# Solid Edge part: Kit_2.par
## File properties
Sűrűség: 0,000 kg/m^3
Pontosság: 0,990
Author: ahadarics
Last saved by: psaghy
Revision: 79
Username: ahadarics
Dokumentum tartalom típus: 0
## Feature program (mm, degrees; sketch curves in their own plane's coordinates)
base feature "unnamed BaseFeature 1"
sketch for "Furat_1" plane through (0, 0, 32.5) normal (0, 0, 1) x-axis (0, -1, 0)
  hole centre (-16.25, 16.25) bore radius 2.4585
hole "Furat_1" nominal diameter 6 finite  VBottomAngle = 118 deg
sketch for "unnamed Hole 1" plane through (0, 0, 32.5) normal (0, 0, 1) x-axis (0, -1, 0)
  hole centre (-16.25, -16.25) bore radius 2.4585
hole "unnamed Hole 1" finite
sketch for "unnamed Hole 2" plane through (0, 0, 32.5) normal (0, 0, 1) x-axis (0, -1, 0)
  hole centre (16.25, -16.25) bore radius 2.4585
hole "unnamed Hole 2" finite
sketch for "unnamed Hole 3" plane through (0, 0, 32.5) normal (0, 0, 1) x-axis (0, -1, 0)
  hole centre (16.25, 16.25) bore radius 2.4585
hole "unnamed Hole 3" finite
pattern "unnamed Pattern 1" of "Furat_1", "unnamed Hole 1", "unnamed Hole 2", "unnamed Hole 3"
sketch for "Furat_5" plane through (23.5, 0.0133, 16.7488) normal (1, 0, 0) x-axis (0, 0, 1)
hole "Furat_5" diameter 9.728 finite  ThreadDepth = 9 mm
chamfer "Letörés_1" setback 0.9
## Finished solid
Body 1: solid body, 352 faces, 833 edges, 526 vertices, 4 internal voids.
  Faces by surface: cylinder 126, plane 118, cone 33, torus 33, spline 30, sphere 10, swept 2
  Edges by curve: curve on surface 298, line 276, circle 245, spline 14
Bounding box of the edges (mm; curved faces can reach further): 47.001 x 47.000 x 30.500, from (-23.5, -23.5, 6) to (23.5005, 23.5, 36.5).
Cylindrical faces by radius (mm): R0.2287 x1, R0.2297 x1, R0.2305 x1, R0.232 x1, R0.2354 x1, R0.2616 x1, R0.2684 x1, R0.2696 x1, R0.274 x1, R0.2809 x1, R0.2869 x1, R0.2897 x2, R0.2949 x1, R0.2975 x1, R0.2999 x1, R0.3047 x1, R0.3049 x1, R0.3054 x1, R0.3191 x1, R0.3251 x1, R0.3471 x1, R0.361 x1, R0.3789 x1, R0.3925 x1, R0.3994 x1, R0.4078 x1, R0.4206 x1, R0.4339 x1, R0.4364 x1, R0.4536 x1, R0.4559 x1, R0.4564 x1, R0.4771 x1, R0.4781 x1, R0.5 x7, R0.5094 x1, R0.5174 x1, R0.5226 x1, R0.5354 x1, R0.5534 x1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
Conical faces (half-angle, radius in mm at the cone's reference point): 5.1549 deg R0.4847 x1, 27.5528 deg R20.5 x4, 30 deg R4.0866 x1, 30 deg R7.8557 x1, 45 deg R1.1 x1, 45 deg R2.3 x1, 45 deg R2.4 x1, 45 deg R3.25 x8, 45 deg R4.85 x8, 45 deg R5.183 x1, 45 deg R6.15 x1, 59 deg R1.75 x1, 59 deg R2.4585 x4
Toroidal faces (ring radius, tube radius in mm): R0.7228 r0.5 x1, R0.8364 r0.5 x1, R1.4663 r0.5006 x3, R3.3 r0.3 x4, R3.6 r0.4 x1, R3.7 r0.3 x1, R4.95 r0.2 x4, R5.65 r0.5 x4, R7.75 r0.5 x1, R8 r0.5 x1, R14.5 r0.5 x1, R15.5 r0.5 x1, R18 r1 x3, R22.5 r1 x6, R23.8031 r0.5 x1
Spherical faces by radius (mm): R0.5 x4, R1 x6
Planar faces by outward normal: +x 19, +y 9, +z 25, -x 2, -y 9, -z 14, oblique 40
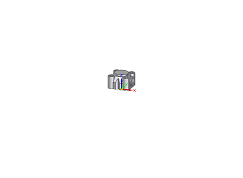
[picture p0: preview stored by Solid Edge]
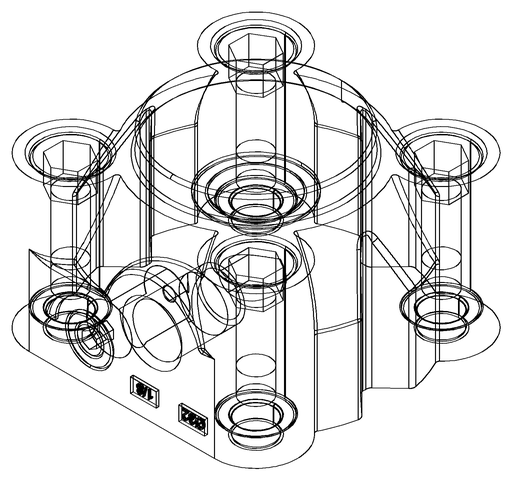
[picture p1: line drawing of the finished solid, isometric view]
